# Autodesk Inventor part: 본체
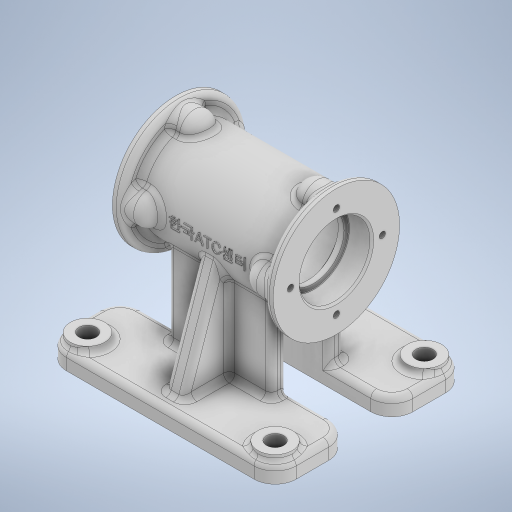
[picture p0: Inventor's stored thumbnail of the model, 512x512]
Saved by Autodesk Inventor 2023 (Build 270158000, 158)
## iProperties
Created: 2026-06
Part Number: 본체
Material: 일반
Document SubType Name: Modeling
Designer: 4강의실
Density: 1 g/cm^3
Appearance: 기본값
Author: 4강의실
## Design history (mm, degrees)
sketch "스케치1"
  geometry: L1 (-42, 0)-(-42, 33); L2 (-42, 33)-(-37, 33); L3 (-37, 33)-(-37, 25); L4 (-37, 25)-(37, 25); L5 (37, 25)-(37, 33); L6 (37, 33)-(42, 33); L7 (42, 33)-(42, 0); L8 (42, 0)-(-42, 0); 2 further points
  constraints: 16 end point, 5 perpendicular, 2 point on line, 1 coincident, 1 collinear, 1 horizontal, 1 midpoint, 1 vertical
  dimensions: "d0" = 84 distance between parallel lines of L7 L1; "d1" = 66 diameter of L2 L8; "d2" = 50 diameter of L4 L8; "d3" = 5 distance of L5.end L6.end
revolve "회전1" sketch "스케치1" stored, may be unused: angle "d4" = 90 deg
sketch "스케치3"
  geometry: L1 (-61, -50)-(-70, -50); L2 (-70, -50)-(-70, -11); L3 (-70, -11)-(-61, -11); L4 (-61, -11)-(-61, -50); L5 (0, 0)-(-63.878, 0); L6 (-61, -11)-(-22.45, -11); L7 (-16.248, -19)-(-61, -19); C1 r 33 at (0, 0) reference; A1 r 25 centre (0, 0) between (-22.45, -11) and (-16.248, -19) reference
  constraints: 14 end point, 3 horizontal, 2 parallel, 2 perpendicular, 2 point on circle, 1 point on line
  dimensions: "d12" = 70 distance from line of L2 L5.start; "d13" = 9 distance of L2.end L3.end; "d14" = 39 distance of L1.end L2.end; "d15" = 100 diameter of L1 L5; "d19" = 8 distance between parallel lines of L6 L7
extrude "돌출1" join sketch "스케치3" stored distance "d17" = 120; taper "d18" = 0 deg
extrude "돌출2" join sketch "스케치3" stored distance "d20" = 54; taper "d21" = 0 deg
sketch "스케치4"
  geometry: L1 (-6.346, -24.181)-(-61, -43); L2 (-61, -50)-(-61, -11) reference; L3 (-61, -19)-(-16.248, -19) reference; L4 (-70, -50)-(-61, -50) reference; A1 r 25 centre (0, 0) between (-6.346, -24.181) and (-16.248, -19) reference; 1 further point
  constraints: 2 end point, 1 point on circle, 1 point on line
  dimensions: "d22" = 19 deg angle of L3 L1; "d23" = 7 distance from line of L1.end L4
feature "리브1" sketch "스케치4" dims "d24" = 1, "d25" = 10, "d26" = 0, "d27" = 0, "d28" = 1, "d29" = 1
sketch "스케치5"
  geometry: L1 (0, 0)-(120, 0) reference; L2 (60, 0)-(60, 15.652); L3 (18, -17)-(18, -83) reference; L4 (18, -50)-(3.294, -50); C1 r 9 at (109, -11); C2 r 9 at (11, -11); 1 further point
  constraints: 4 end point, 2 centre point, 2 midpoint, 1 horizontal, 1 symmetric about line, 1 vertical, 1 other
  dimensions: "d30" = 18 diameter of C1; "d31" = 98 diameter of C1.centre L2; "d32" = 78 diameter of C1.centre L4
extrude "돌출3" join sketch "스케치5" distance "d33" = 3; taper "d34" = 0 deg
fillet "모깎기3" dims "d75" = 3
sketch "스케치6"
  geometry: L1 (42, 33)-(42, -33) reference; L2 (32, 32)-(37, 32); L3 (37, 33)-(37, -33) reference; L4 (32, 24)-(24, 24); L5 (37, 25)-(37, -25) reference; L6 (37, 32)-(37, 25); L7 (37, 25)-(24.063, 25); L8 (37, 25)-(-37, 25) reference; A1 r 8 centre (32, 24) between (37, 30.245) and (37, 17.755); A2 r 8 centre (32, 24) between (37, 17.755) and (37, 30.245); 1 further point
  constraints: 8 end point, 7 point on circle, 4 point on line, 2 centre point, 1 horizontal, 1 tangent
  dimensions: "d35" = 16 diameter of A1; "d36" = 24 vertical distance of point (0, 0) L4.start; "d37" = 10 distance from line of L1 L4.start
revolve "회전3" sketch "스케치6" stored, may be unused: angle "d38" = 90 deg
sketch "스케치8"
  geometry: 6 further points
  constraints: 2 vertical alignment, 1 coincident, 7 other
  dimensions: "d48" = 24 distance of point (0, 24) point (0, 0); "d51" = 360 deg dimension on point (0, 0) point (0, 24) (derived)
hole "구멍1" sketch "스케치8" at (0, 24), (-24, 0), (0, -24), (24, 0) diameter "d53" = 3.242; stored, may be unused: countersink angle "d57" = 90 deg, drill point angle "d59" = 118 deg; dims "d54" = 8, "d55" = 4, "d56" = 2, "d58" = 10
sketch "스케치7"
  geometry: L1 (42, 33)-(42, -33) reference; L2 (42, 0)-(30, 0); L3 (30, 0)-(30, 18.5); L4 (30, 18.5)-(42, 18.5); L5 (42, 18.5)-(42, 0); L6 (30, 0)-(27, 0); L7 (27, 0)-(27, 16); L8 (27, 16)-(30, 16); L9 (30, 16)-(30, 0); L10 (27, 0)-(-27, 0); L11 (-27, 0)-(-27, 20); L12 (-27, 20)-(27, 20); L13 (27, 20)-(27, 0); L14 (-27, 0)-(-30, 0); L15 (-30, 0)-(-30, 16); L16 (-30, 16)-(-27, 16); L17 (-27, 16)-(-27, 0); L18 (-42, 33)-(-42, -33) reference; L19 (-30, 0)-(-42, 0); L20 (-42, 0)-(-42, 18.5); L21 (-42, 18.5)-(-30, 18.5); L22 (-30, 18.5)-(-30, 0); 7 further points
  constraints: 40 end point, 10 parallel, 5 horizontal, 5 perpendicular, 3 point on line, 2 collinear, 1 midpoint
  dimensions: "d42" = 37 diameter of L4 L2; "d43" = 12 distance between parallel lines of L3 L5; "d44" = 54 distance of L11.end L12.end; "d45" = 40 diameter of L12 L10; "d46" = 32 diameter of L8 L6
revolve "회전4" sketch "스케치7" stored, may be unused: angle "d47" = 90 deg
sketch "스케치9"
  geometry: C1 r 9 at (0, 0) reference; C2 r 9 at (-98, 0) reference; C3 r 9 at (-98, -78) reference; C4 r 9 at (0, -78) reference; 5 further points
  constraints: 4 coincident
hole "구멍2" sketch "스케치9" at (0, 0), (-98, 0), (-98, -78), (0, -78) diameter "d60" = 9; stored, may be unused: countersink angle "d64" = 90 deg, drill point angle "d66" = 118 deg; dims "d61" = 8, "d62" = 4, "d63" = 2, "d65" = 10
chamfer "모따기1" distance "d67" = 1; stored, may be unused: second distance "d68" = 2, angle "d69" = 45 deg
fillet "모깎기6" dims "d78" = 11
fillet "모깎기1" dims "d73" = 0.3
fillet "모깎기2" dims "d74" = 3
fillet "모깎기4" dims "d76" = 3
fillet "모깎기5" dims "d77" = 3
fillet "모깎기7" dims "d79" = 3
fillet "모깎기8" dims "d80" = 3
fillet "모깎기9" dims "d81" = 3
node "작업 평면1"
sketch "스케치10"
  geometry: L1 (-49, -70)-(49, -70) reference; 2 further points
  constraints: 1 coincident, 1 other
  dimensions: "d83" = 70 distance from line of L1 point (0, 0)
feature "엠보싱1" sketch "스케치10" dims "d0" = 84, "d1" = 66, "d2" = 50, "d3" = 5, "d12" = 70, "d13" = 9, "d14" = 39, "d15" = 100, "d19" = 8, "d84" = 0.5, "d85" = 0
sketch "스케치11"
  geometry: L1 (-26.833, 11)-(-64, 11) reference; L2 (-50, 11)-(-50, -11); L3 (-64, -11)-(-26.833, -11) reference; L4 (-70, -22)-(-70, -11) reference; 1 further point
  constraints: 2 end point, 2 point on line, 1 vertical
  dimensions: "d86" = 20 distance between parallel lines of L2 L4
feature "리브2" sketch "스케치11" dims "d87" = 1, "d88" = 10, "d89" = 0, "d90" = 0, "d91" = 1, "d92" = 1
fillet "모깎기10" dims "d93" = 3
fillet "모깎기11" dims "d94" = 3
node "솔리드1"
pattern_circular "원형 패턴1" dims angle "d40" = 360 deg
mirror "미러1"
mirror "미러2"
mirror "미러3"
feature "A9D066F2-1C7D-4E18-AEED-F7BC21143FA4" dims "d60" = 9, "d61" = 8, "d62" = 4, "d63" = 2, "d64" = 90 deg, "d65" = 10, "d66" = 118 deg
other parameters: "d82" = 85.25
